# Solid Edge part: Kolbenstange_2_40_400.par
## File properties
Username: ahadarics
Dokumentum tartalom típus: 0
Author: ahadarics
Last saved by: ahadarics
Revision: 87
Sűrűség: 0,000 kg/m^3
Pontosság: 0,990
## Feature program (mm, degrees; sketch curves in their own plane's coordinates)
base feature "unnamed BaseFeature 1"
thread "unnamed Thread 1"
chamfer "Letörés_1"  SetBackValue2 = 20 deg
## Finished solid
Body 1: solid body, 21 faces, 37 edges, 20 vertices.
  Faces by surface: plane 8, cylinder 5, cone 4, torus 4
  Edges by curve: circle 20, line 11, curve on surface 4, ellipse 2
Bounding box of the edges (mm; curved faces can reach further): 40.000 x 40.000 x 486.000, from (-20, -20, -56) to (20, 20, 430).
Cylindrical faces by radius (mm): R5 x1, R6 x1, R7.75 x1, R8 x1, R20 x1
Conical faces (half-angle, radius in mm at the cone's reference point): 20 deg R4.9991 x1, 30 deg R7.875 x1, 45 deg R19.6 x1, 60 deg R5.5 x1
Toroidal faces (ring radius, tube radius in mm): R5.4 r0.4 x2, R6.55 r1.2 x2
Planar faces by outward normal: +x 1, +z 3, -x 1, -z 1, oblique 2
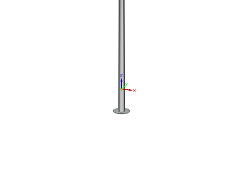
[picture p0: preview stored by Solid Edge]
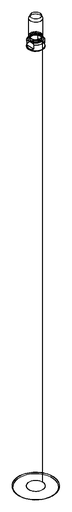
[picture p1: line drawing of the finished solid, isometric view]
